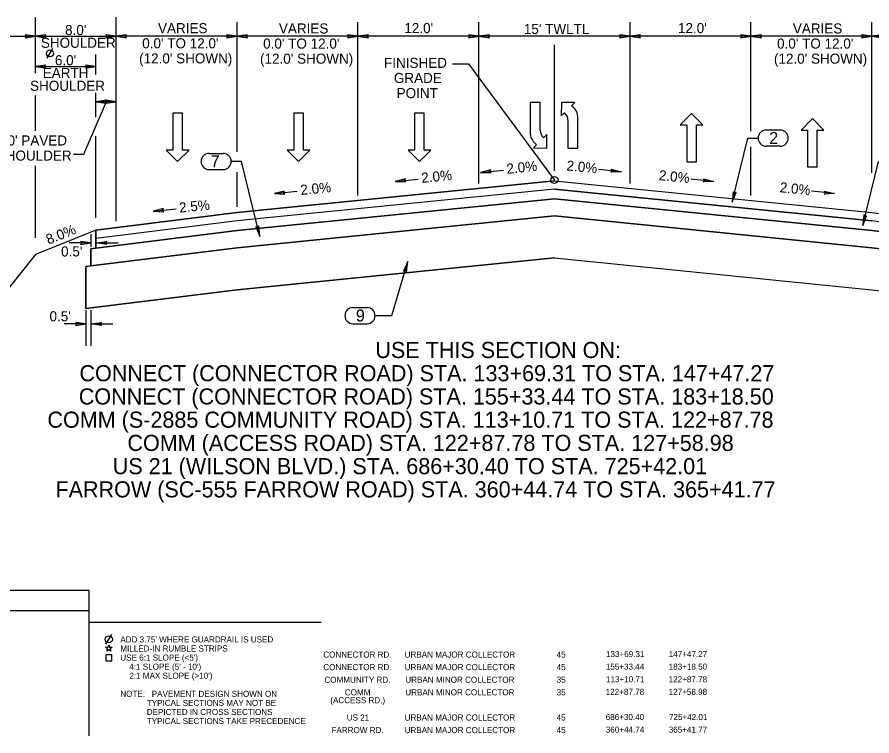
# Model space of a CAD drawing. Extents: x 2003207 to 2014043, y 843846 to 860154.
# Drawn here: x 2013648.6 to 2013733.4, y 843966 to 844037.3 of the extents above; entities that cross this region are included whole.
import ezdxf

# ---------------------------------------------------------------- set-up
doc = ezdxf.new("R2010")
doc.units = 0
for name, color, linetype in [('RD_EX_Road_txCode', 7, 'Continuous'), ('RD_QTY_Base_Course', 7, 'Continuous'), ('RD_QTY_ConcPave', 7, 'Continuous'), ('RD_QTY_Intermediate', 7, 'Continuous'), ('RD_QTY_PermVeg', 7, 'Continuous'), ('RD_QTY_Surf_Course', 7, 'Continuous'), ('RD_SHT_Bndy', 7, 'Continuous'), ('RD_SHT_TX', 7, 'Continuous'), ('RD_TX_Misc2', 7, 'Continuous'), ('RD_TX_TypSect', 7, 'Continuous')]:
    doc.layers.add(name, color=color, linetype=linetype)

msp = doc.modelspace()

# ---------------------------------------------------------------- linework, layer by layer
at = {"layer": 'RD_EX_Road_txCode'}
msp.add_line((2013657.384, 843975.107), (2013657.95, 843976.05), dxfattribs=at)
for points in [[(2013657.334, 843974.786), (2013657.589, 843974.786), (2013657.667, 843975.028), (2013657.746, 843974.786), (2013658, 843974.786), (2013657.794, 843974.637), (2013657.873, 843974.395), (2013657.667, 843974.544), (2013657.462, 843974.395), (2013657.54, 843974.637)], [(2013657.367, 843973.452), (2013657.967, 843973.452), (2013657.967, 843974.052), (2013657.367, 843974.052)]]:
    msp.add_lwpolyline(points, close=True, dxfattribs=at)
for centre in [(2013701.892, 844021.17), (2013657.667, 843975.578)]:
    msp.add_circle(centre, 0.35, dxfattribs=at)
at = {"layer": 'RD_QTY_Base_Course'}
for p, q in [((2013701.892, 844019.306), (2013670.392, 844016.156)), ((2013733.392, 844016.156), (2013701.892, 844019.306)), ((2013701.892, 844017.601), (2013670.392, 844014.451)), ((2013670.392, 844014.451), (2013701.892, 844017.601)), ((2013733.392, 844014.451), (2013701.892, 844017.601)), ((2013701.892, 844017.601), (2013733.392, 844014.451)), ((2013670.392, 844016.156), (2013656.392, 844014.406)), ((2013747.392, 844014.406), (2013733.392, 844016.156)), ((2013670.392, 844014.451), (2013655.892, 844012.639)), ((2013655.892, 844012.639), (2013670.392, 844014.451)), ((2013656.392, 844014.406), (2013655.892, 844014.343)), ((2013655.892, 844014.343), (2013655.892, 844012.639)), ((2013747.892, 844012.639), (2013733.392, 844014.451)), ((2013733.392, 844014.451), (2013747.892, 844012.639)), ((2013701.892, 844013.434), (2013670.392, 844010.284)), ((2013670.392, 844010.284), (2013701.892, 844013.434)), ((2013701.892, 844013.434), (2013733.392, 844010.284)), ((2013701.892, 844013.434), (2013733.392, 844010.284)), ((2013655.392, 844012.576), (2013655.892, 844012.639)), ((2013655.892, 844012.639), (2013655.392, 844012.576)), ((2013655.392, 844008.409), (2013655.392, 844012.576)), ((2013655.392, 844012.576), (2013655.392, 844008.409)), ((2013670.392, 844010.284), (2013655.392, 844008.409)), ((2013655.392, 844008.409), (2013670.392, 844010.284)), ((2013733.392, 844010.284), (2013748.392, 844008.409))]:
    msp.add_line(p, q, dxfattribs=at)
at = {"layer": 'RD_QTY_ConcPave'}
for p, q in [((2013701.892, 844017.601), (2013670.392, 844014.451)), ((2013701.892, 844017.601), (2013733.392, 844014.451)), ((2013670.392, 844014.451), (2013655.892, 844012.639)), ((2013655.892, 844014.343), (2013656.392, 844014.406)), ((2013655.892, 844012.639), (2013655.892, 844014.343))]:
    msp.add_line(p, q, dxfattribs=at)
at = {"layer": 'RD_QTY_Intermediate'}
for p, q in [((2013701.892, 844020.253), (2013670.392, 844017.103)), ((2013701.892, 844019.306), (2013670.392, 844016.156)), ((2013670.392, 844016.156), (2013701.892, 844019.306)), ((2013701.892, 844019.306), (2013733.392, 844016.156)), ((2013701.892, 844019.306), (2013733.392, 844016.156)), ((2013670.392, 844017.103), (2013656.392, 844015.353)), ((2013670.392, 844016.156), (2013656.392, 844014.406)), ((2013656.392, 844014.406), (2013670.392, 844016.156)), ((2013733.392, 844016.156), (2013747.392, 844014.406)), ((2013656.392, 844014.406), (2013656.392, 844015.353)), ((2013656.392, 844015.353), (2013656.392, 844014.406))]:
    msp.add_line(p, q, dxfattribs=at)
msp.add_lwpolyline([(2013747.392, 844015.353), (2013733.392, 844017.103), (2013701.892, 844020.253)], dxfattribs=at)
at = {"layer": 'RD_QTY_PermVeg'}
for p, q in [((2013656.392, 844016.186), (2013650.392, 844013.786)), ((2013650.392, 844013.786), (2013636.392, 843996.286))]:
    msp.add_line(p, q, dxfattribs=at)
at = {"layer": 'RD_QTY_Surf_Course'}
for p, q in [((2013701.892, 844021.086), (2013670.392, 844017.936)), ((2013701.892, 844021.086), (2013733.392, 844017.936)), ((2013701.892, 844020.253), (2013670.392, 844017.103)), ((2013701.892, 844020.253), (2013733.392, 844017.103)), ((2013670.392, 844017.936), (2013656.392, 844016.186)), ((2013733.392, 844017.936), (2013747.392, 844016.186)), ((2013670.392, 844017.103), (2013656.392, 844015.353)), ((2013656.392, 844016.186), (2013656.392, 844015.353))]:
    msp.add_line(p, q, dxfattribs=at)
msp.add_lwpolyline([(2013656.392, 844015.353), (2013656.392, 844016.186), (2013670.392, 844017.936), (2013701.892, 844021.086), (2013733.392, 844017.936), (2013747.392, 844016.186), (2013747.392, 844015.353), (2013733.392, 844017.103), (2013701.892, 844020.253), (2013670.392, 844017.103)], close=True, dxfattribs=at)
at = {"layer": 'RD_SHT_Bndy'}
for p, q in [((2013655.72, 843980.41), (2013615.72, 843980.41)), ((2013655.72, 843978.41), (2013655.72, 843980.41)), ((2013655.72, 843978.41), (2013615.72, 843978.41)), ((2013655.72, 843965.992), (2013655.72, 843978.41)), ((2013678.754, 843977.242), (2013655.754, 843977.242))]:
    msp.add_line(p, q, dxfattribs=at)
at = {"layer": 'RD_TX_Misc2'}
for p, q in [((2013724.294, 844026.124), (2013722.894, 844026.124)), ((2013724.294, 844024.524), (2013722.894, 844024.524)), ((2013667.619, 844023.811), (2013669.019, 844023.811)), ((2013667.619, 844022.211), (2013669.019, 844022.211)), ((2013681.893, 844008.508), (2013683.293, 844008.508)), ((2013681.893, 844006.908), (2013683.293, 844006.908))]:
    msp.add_line(p, q, dxfattribs=at)
for centre, start, end in [((2013722.894, 844025.324), 90, 270), ((2013724.294, 844025.324), 270, 90), ((2013667.619, 844023.011), 90, 270), ((2013669.019, 844023.011), 270, 90), ((2013681.893, 844007.708), 90, 270), ((2013683.293, 844007.708), 270, 90)]:
    msp.add_arc(centre, 0.8, start, end, dxfattribs=at)
at = {"layer": 'RD_TX_TypSect'}
for p, q in [((2013650.392, 844031.766), (2013650.392, 844037.34)), ((2013658.392, 844017.093), (2013658.392, 844037.34)), ((2013670.392, 844023.962), (2013670.392, 844036.824)), ((2013682.392, 844019.636), (2013682.392, 844036.824)), ((2013694.392, 844020.836), (2013694.392, 844036.824)), ((2013709.392, 844020.836), (2013709.392, 844036.824)), ((2013721.392, 844026.019), (2013721.392, 844036.824)), ((2013733.392, 844021.871), (2013733.392, 844036.824)), ((2013636.392, 844035.433), (2013650.392, 844035.433)), ((2013650.392, 844035.433), (2013658.392, 844035.433)), ((2013670.392, 844035.433), (2013658.392, 844035.433)), ((2013682.392, 844035.433), (2013670.392, 844035.433)), ((2013694.392, 844035.433), (2013682.392, 844035.433)), ((2013709.392, 844035.433), (2013694.392, 844035.433)), ((2013721.392, 844035.433), (2013709.392, 844035.433)), ((2013733.392, 844035.433), (2013721.392, 844035.433)), ((2013745.392, 844035.433), (2013733.392, 844035.433)), ((2013701.892, 844022.086), (2013701.892, 844034.58)), ((2013651.544, 844033.266), (2013652.11, 844034.209)), ((2013656.392, 844031.639), (2013656.392, 844033.619)), ((2013650.392, 844032.433), (2013656.392, 844032.433)), ((2013650.392, 844026.063), (2013650.392, 844029.561)), ((2013656.392, 844027.411), (2013656.392, 844029.829)), ((2013658.392, 844028.933), (2013656.392, 844028.933)), ((2013699.489, 844028.875), (2013699.489, 844025.71)), ((2013700.479, 844028.875), (2013699.489, 844028.875)), ((2013700.479, 844026.13), (2013700.479, 844028.875)), ((2013702.579, 844028.875), (2013702.564, 844027.525)), ((2013703.899, 844028.86), (2013702.579, 844028.875)), ((2013703.584, 844028.545), (2013703.899, 844028.86)), ((2013702.564, 844027.525), (2013702.879, 844027.84)), ((2013703.224, 844027.09), (2013703.224, 844024.345)), ((2013704.214, 844024.345), (2013704.214, 844027.51)), ((2013656.392, 844017.426), (2013656.392, 844025.534)), ((2013701.139, 844025.695), (2013700.824, 844025.38)), ((2013701.124, 844024.345), (2013701.139, 844025.695)), ((2013700.119, 844024.675), (2013699.804, 844024.36)), ((2013699.804, 844024.36), (2013701.124, 844024.345)), ((2013703.224, 844024.345), (2013704.214, 844024.345)), ((2013721.392, 844019.636), (2013721.392, 844024.448)), ((2013650.392, 844015.417), (2013650.392, 844022.586)), ((2013670.392, 844018.522), (2013670.392, 844021.961)), ((2013694.549, 844021.926), (2013696.825, 844022.154)), ((2013708.529, 844021.99), (2013706.252, 844022.218)), ((2013686.097, 844021.026), (2013688.373, 844021.253)), ((2013717.688, 844021.026), (2013715.411, 844021.253)), ((2013674.097, 844019.826), (2013676.373, 844020.053)), ((2013729.688, 844019.826), (2013727.411, 844020.053)), ((2013662.073, 844018.073), (2013664.35, 844018.301)), ((2013655.892, 844015.78), (2013655.892, 844014.552)), ((2013655.892, 844014.921), (2013653.725, 844014.921)), ((2013656.422, 844014.921), (2013658.59, 844014.921)), ((2013655.392, 844008.252), (2013655.392, 844004.717)), ((2013655.892, 844008.252), (2013655.892, 844004.717)), ((2013655.392, 844006.88), (2013653.225, 844006.88)), ((2013655.892, 844006.88), (2013658.06, 844006.88))]:
    msp.add_line(p, q, dxfattribs=at)
for points in [[(2013650.392, 844035.433), (2013649.354, 844035.583), (2013649.514, 844035.433), (2013649.354, 844035.283)], [(2013650.392, 844035.433), (2013651.431, 844035.283), (2013651.271, 844035.433), (2013651.431, 844035.583)], [(2013658.392, 844035.433), (2013657.354, 844035.583), (2013657.514, 844035.433), (2013657.354, 844035.283)], [(2013658.392, 844035.433), (2013659.431, 844035.283), (2013659.271, 844035.433), (2013659.431, 844035.583)], [(2013670.392, 844035.433), (2013669.354, 844035.583), (2013669.514, 844035.433), (2013669.354, 844035.283)], [(2013670.392, 844035.433), (2013671.431, 844035.283), (2013671.271, 844035.433), (2013671.431, 844035.583)], [(2013682.392, 844035.433), (2013681.354, 844035.583), (2013681.514, 844035.433), (2013681.354, 844035.283)], [(2013682.392, 844035.433), (2013683.431, 844035.283), (2013683.271, 844035.433), (2013683.431, 844035.583)], [(2013694.392, 844035.433), (2013693.354, 844035.583), (2013693.514, 844035.433), (2013693.354, 844035.283)], [(2013694.392, 844035.433), (2013695.431, 844035.283), (2013695.271, 844035.433), (2013695.431, 844035.583)], [(2013709.392, 844035.433), (2013708.354, 844035.583), (2013708.514, 844035.433), (2013708.354, 844035.283)], [(2013709.392, 844035.433), (2013710.431, 844035.283), (2013710.271, 844035.433), (2013710.431, 844035.583)], [(2013721.392, 844035.433), (2013720.354, 844035.583), (2013720.514, 844035.433), (2013720.354, 844035.283)], [(2013721.392, 844035.433), (2013722.431, 844035.283), (2013722.271, 844035.433), (2013722.431, 844035.583)], [(2013733.392, 844035.433), (2013732.354, 844035.583), (2013732.514, 844035.433), (2013732.354, 844035.283)], [(2013733.392, 844035.433), (2013734.431, 844035.283), (2013734.271, 844035.433), (2013734.431, 844035.583)], [(2013650.392, 844032.433), (2013651.431, 844032.283), (2013651.271, 844032.433), (2013651.431, 844032.583)], [(2013656.392, 844032.433), (2013655.354, 844032.583), (2013655.514, 844032.433), (2013655.354, 844032.283)], [(2013656.392, 844028.933), (2013657.431, 844028.783), (2013657.271, 844028.933), (2013657.431, 844029.083)], [(2013658.392, 844028.933), (2013657.354, 844029.083), (2013657.514, 844028.933), (2013657.354, 844028.783)], [(2013664.974, 844027.809), (2013664.014, 844027.809), (2013664.014, 844024.14), (2013663.363, 844024.14), (2013664.494, 844023.009), (2013665.625, 844024.14), (2013664.974, 844024.14)], [(2013676.974, 844027.809), (2013676.014, 844027.809), (2013676.014, 844024.14), (2013675.363, 844024.14), (2013676.494, 844023.009), (2013677.625, 844024.14), (2013676.974, 844024.14)], [(2013688.974, 844027.809), (2013688.014, 844027.809), (2013688.014, 844024.14), (2013687.363, 844024.14), (2013688.494, 844023.009), (2013689.625, 844024.14), (2013688.974, 844024.14)], [(2013715.014, 844022.961), (2013715.974, 844022.961), (2013715.974, 844026.63), (2013716.625, 844026.63), (2013715.494, 844027.761), (2013714.363, 844026.63), (2013715.014, 844026.63)], [(2013727.014, 844022.461), (2013727.974, 844022.461), (2013727.974, 844026.13), (2013728.625, 844026.13), (2013727.494, 844027.261), (2013726.363, 844026.13), (2013727.014, 844026.13)], [(2013694.549, 844021.926), (2013695.597, 844021.88), (2013695.423, 844022.013), (2013695.567, 844022.179)], [(2013708.529, 844021.99), (2013707.48, 844021.945), (2013707.654, 844022.078), (2013707.51, 844022.243)], [(2013686.097, 844021.026), (2013687.145, 844020.98), (2013686.971, 844021.113), (2013687.115, 844021.278)], [(2013717.688, 844021.026), (2013716.639, 844020.98), (2013716.814, 844021.113), (2013716.669, 844021.278)], [(2013674.097, 844019.826), (2013675.145, 844019.78), (2013674.971, 844019.913), (2013675.115, 844020.078)], [(2013719.529, 844018.967), (2013719.921, 844019.94), (2013719.738, 844019.821), (2013719.63, 844020.012)], [(2013729.688, 844019.826), (2013728.639, 844019.78), (2013728.814, 844019.913), (2013728.669, 844020.078)], [(2013662.073, 844018.073), (2013663.121, 844018.027), (2013662.947, 844018.161), (2013663.092, 844018.326)], [(2013732.478, 844016.654), (2013732.871, 844017.627), (2013732.687, 844017.508), (2013732.579, 844017.699)], [(2013672.651, 844015.564), (2013672.549, 844016.609), (2013672.442, 844016.417), (2013672.258, 844016.537)], [(2013655.892, 844014.921), (2013654.854, 844015.07), (2013655.014, 844014.921), (2013654.854, 844014.771)], [(2013656.422, 844014.921), (2013657.461, 844015.07), (2013657.301, 844014.921), (2013657.461, 844014.771)], [(2013687.346, 844013.086), (2013686.908, 844012.132), (2013687.097, 844012.243), (2013687.196, 844012.047)], [(2013655.392, 844006.88), (2013654.354, 844007.03), (2013654.514, 844006.88), (2013654.354, 844006.73)], [(2013655.892, 844006.88), (2013656.931, 844007.03), (2013656.771, 844006.88), (2013656.931, 844006.73)]]:
    msp.add_lwpolyline(points, close=True, dxfattribs=at)
for points in [[(2013691.787, 844032.69), (2013693.356, 844032.69), (2013701.892, 844021.17)], [(2013657.392, 844028.933), (2013655.152, 844023.687), (2013654.164, 844023.687)], [(2013719.529, 844018.967), (2013721.085, 844025.324), (2013722.094, 844025.324)], [(2013672.651, 844015.564), (2013670.828, 844023.011), (2013669.819, 844023.011)], [(2013732.478, 844016.654), (2013734.034, 844023.011), (2013735.043, 844023.011)], [(2013684.093, 844007.708), (2013685.759, 844007.708), (2013687.346, 844013.086)]]:
    msp.add_lwpolyline(points, dxfattribs=at)
msp.add_circle((2013651.827, 844033.738), 0.35, dxfattribs=at)
for centre, radius, start, end in [((2013702.661, 844027.272), 1.576, 8.67607, 53.98777), ((2013702.247, 844027.093), 0.983, 0, 49.65818), ((2013701.456, 844026.127), 0.983, 180, 229.65817), ((2013701.042, 844025.947), 1.576, 188.67607, 233.98777)]:
    msp.add_arc(centre, radius, start, end, dxfattribs=at)

# ---------------------------------------------------------------- texts
at = {"layer": 'RD_EX_Road_txCode'}
for s, height, p in [('USE THIS SECTION ON:', 1.6, (2013684.116, 844003.497)), ('CONNECT (CONNECTOR ROAD) STA. 133+69.31 TO STA. 147+47.27', 1.6, (2013654.749, 844001.192)), ('CONNECT (CONNECTOR ROAD) STA. 155+33.44 TO STA. 183+18.50', 1.6, (2013654.686, 843998.886)), ('COMM (S-2885 COMMUNITY ROAD) STA. 113+10.71 TO STA. 122+87.78', 1.6, (2013651.574, 843996.581)), ('COMM (ACCESS ROAD) STA. 122+87.78 TO STA. 127+58.98', 1.6, (2013659.511, 843994.275)), ('US 21 (WILSON BLVD.) STA. 686+30.40 TO STA. 725+42.01', 1.6, (2013658.056, 843991.97)), ('FARROW (SC-555 FARROW ROAD) STA. 360+44.74 TO STA. 365+41.77', 1.6, (2013652.368, 843989.664)), ("ADD 3.75' WHERE GUARDRAIL IS USED", 0.6, (2013658.808, 843975.268)), ('MILLED-IN RUMBLE STRIPS', 0.6, (2013658.808, 843974.368)), ("USE 6:1 SLOPE (<5')", 0.6, (2013658.808, 843973.468)), ("    4:1 SLOPE (5' - 10')", 0.6, (2013658.808, 843972.568)), ("    2:1 MAX SLOPE (>10')", 0.6, (2013658.808, 843971.668)), ('NOTE:   PAVEMENT DESIGN SHOWN ON', 0.6, (2013658.808, 843969.868)), (' TYPICAL SECTIONS MAY NOT BE ', 0.6, (2013661.208, 843968.968)), (' DEPICTED IN CROSS SECTIONS', 0.6, (2013661.208, 843968.068)), (' TYPICAL SECTIONS TAKE PRECEDENCE', 0.6, (2013661.208, 843967.168))]:
    msp.add_text(s, height=height, dxfattribs=at).set_placement(p)
at = {"layer": 'RD_SHT_TX'}
for s, p in [('CONNECTOR RD.', (2013678.95, 843973.768)), ('URBAN MAJOR COLLECTOR', (2013687.023, 843973.768)), ('45', (2013702.109, 843973.768)), ('133+69.31', (2013707.004, 843973.817)), ('147+47.27', (2013713.232, 843973.817)), ('CONNECTOR RD.', (2013678.95, 843972.518)), ('URBAN MAJOR COLLECTOR', (2013687.023, 843972.518)), ('45', (2013702.109, 843972.518)), ('155+33.44', (2013706.987, 843972.567)), ('183+18.50', (2013713.226, 843972.567)), ('COMMUNITY RD.', (2013679.063, 843971.268)), ('URBAN MINOR COLLECTOR', (2013687.091, 843971.268)), ('35', (2013702.109, 843971.268)), ('113+10.71', (2013707.004, 843971.317)), ('122+87.78', (2013713.226, 843971.317)), ('(ACCESS RD.)', (2013679.646, 843969.236)), ('COMM ', (2013681.095, 843970.017)), ('URBAN MINOR COLLECTOR', (2013687.091, 843970.018)), ('35', (2013702.109, 843970.018)), ('122+87.78', (2013706.976, 843970.067)), ('127+58.98', (2013713.226, 843970.067)), ('686+30.40', (2013706.976, 843967.567)), ('725+42.01', (2013713.254, 843967.567)), ('US 21', (2013681.276, 843967.518)), ('URBAN MAJOR COLLECTOR', (2013687.023, 843967.518)), ('45', (2013702.109, 843967.518)), ('FARROW RD.', (2013679.765, 843966.268)), ('URBAN MAJOR COLLECTOR', (2013687.023, 843966.268)), ('45', (2013702.109, 843966.268)), ('360+44.74', (2013706.987, 843966.317)), ('365+41.77', (2013713.232, 843966.317))]:
    msp.add_text(s, height=0.6, dxfattribs=at).set_placement(p)
at = {"layer": 'RD_TX_Misc2'}
for s, p in [('2', (2013723.198, 844024.739)), ('7', (2013667.775, 844022.426)), ('9', (2013682.184, 844007.123))]:
    msp.add_text(s, height=1.2, dxfattribs=at).set_placement(p)
at = {"layer": 'RD_TX_TypSect'}
for s, p in [("8.0'", (2013653.324, 844035.558)), ('VARIES', (2013662.548, 844035.74)), ('VARIES', (2013674.548, 844035.713)), ("12.0'", (2013686.994, 844035.75)), ("15' TWLTL", (2013698.855, 844035.656)), ("12.0'", (2013714.146, 844035.75)), ('VARIES', (2013725.548, 844035.713)), ('SHOULDER', (2013650.924, 844034.291)), ("0.0' TO 12.0'", (2013660.981, 844034.24)), ("0.0' TO 12.0'", (2013672.981, 844034.213)), ("0.0' TO 12.0'", (2013723.981, 844034.213)), ("6.0'", (2013652.317, 844032.558)), ("(12.0' SHOWN)", (2013660.674, 844032.74)), ("(12.0' SHOWN)", (2013672.674, 844032.713)), ("(12.0' SHOWN)", (2013723.674, 844032.713)), ('FINISHED', (2013684.979, 844032.296)), ('EARTH', (2013651.113, 844031.291)), ('GRADE', (2013685.956, 844030.796)), ('SHOULDER', (2013649.853, 844030.023)), ('POINT', (2013686.231, 844029.296)), ("2.0' PAVED", (2013646.502, 844024.594)), ('SHOULDER', (2013646.542, 844023.094)), ("0.5'", (2013652.933, 844013.582)), ("0.5'", (2013651.781, 844007.144))]:
    msp.add_text(s, height=1, dxfattribs=at).set_placement(p)
for s, rotation, p in [('2.0%', 5.71059, (2013697.182, 844021.779)), ('2.0%', 354.28941, (2013703.052, 844022.128)), ('2.0%', 5.71059, (2013688.73, 844020.879)), ('2.0%', 354.28941, (2013712.211, 844021.163)), ('2.0%', 5.71059, (2013676.73, 844019.679)), ('2.0%', 354.28941, (2013724.211, 844019.963)), ('2.5%', 5.71059, (2013664.691, 844017.925)), ('8.0%', 21.80141, (2013651.674, 844014.746))]:
    msp.add_text(s, height=1, rotation=rotation, dxfattribs=at).set_placement(p)

doc.saveas('drawing.dxf')
